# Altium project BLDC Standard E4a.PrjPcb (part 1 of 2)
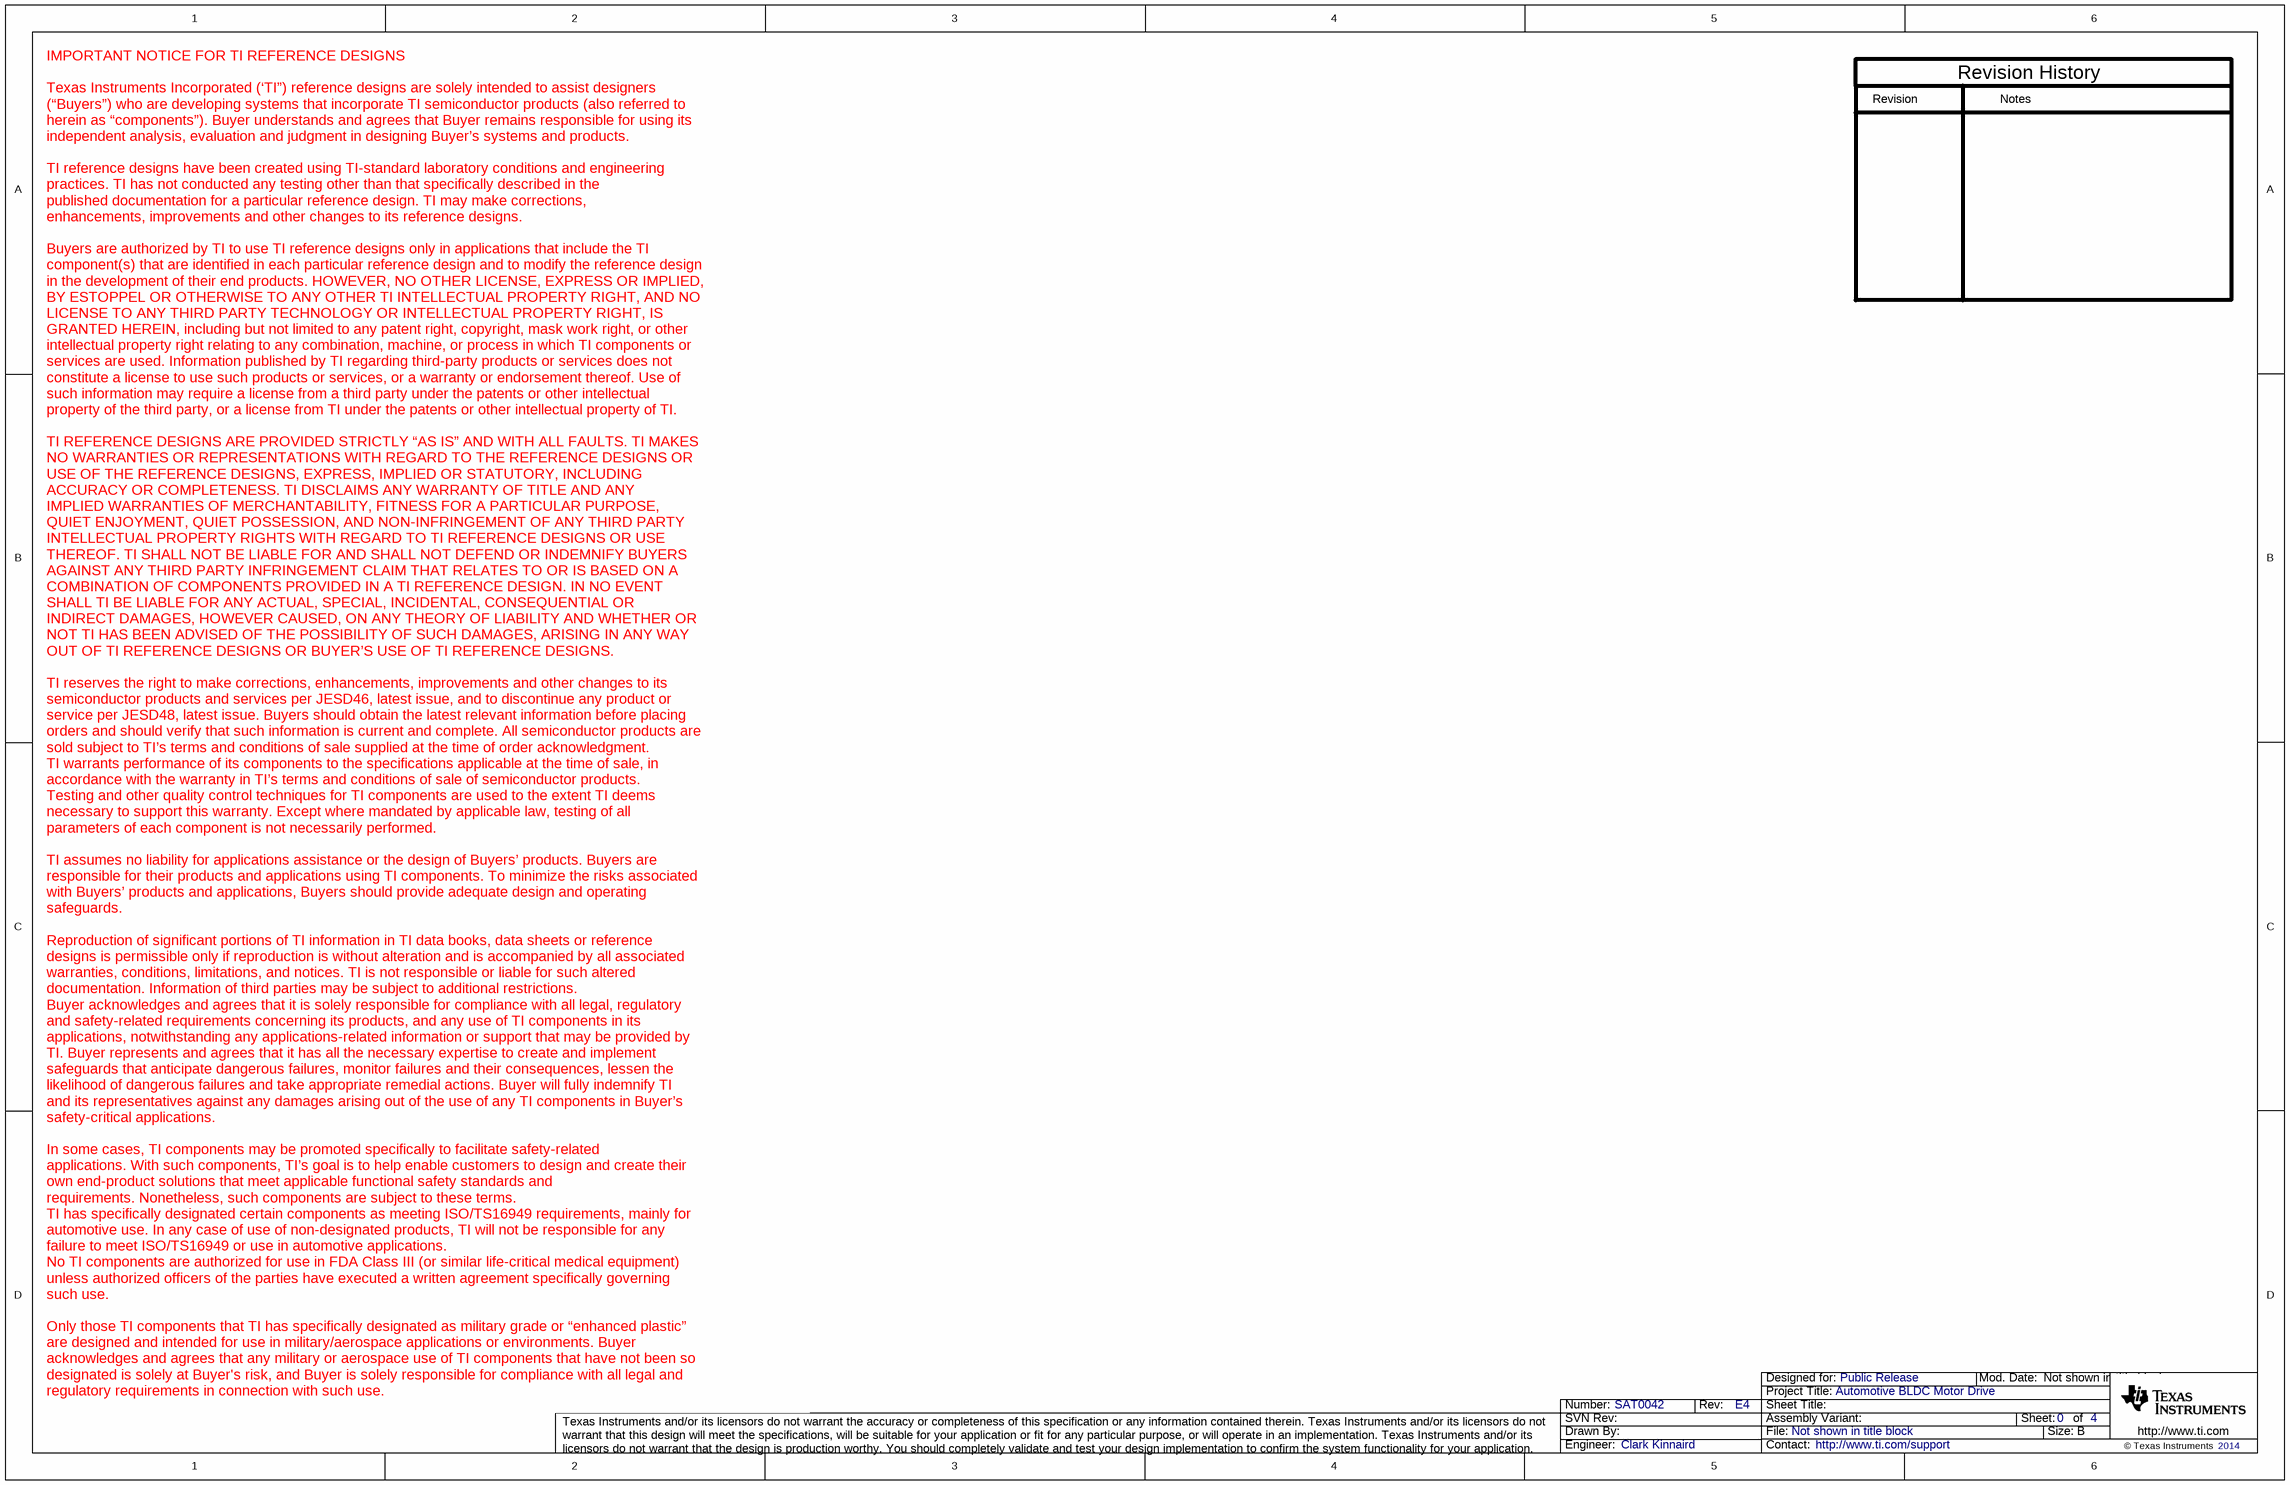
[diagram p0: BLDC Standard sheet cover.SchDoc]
CopyrightYear: 2014; PCB_Layout: Krypton Solutions LLC; PCB_Rev: E4; PRJ_Customer: Public Release; PRJ_Engineer: Clark Kinnaird; PRJ_Number: SAT0042; PRJ_Title: Automotive BLDC Motor Drive; SCH_Rev: E4; TechSupport: http://www.ti.com/support
6 sheets, 212 parts. Net scope: global (net labels, ports and power ports of the same name join across sheets).
Board file: BLDC Standard.PcbDoc
Sheets:
  BLDC Standard sheet cover.SchDoc
  Hardware_ANSI-B.SchDoc
  BLDC Standard sheet 1.SchDoc
  BLDC Standard sheet 2.SchDoc
  BLDC Standard sheet 3.SchDoc
  BLDC Standard sheet 4.SchDoc

## Sheet BLDC Standard sheet cover.SchDoc
size 431 x 279 mm; Date: Not shown in title block; ApprovedBy: Not shown in title block; CheckedBy: Not shown in title block; Author: Not shown in title block; CompanyName: Not shown in title block; Engineer: Not shown in title block; Organization: Not shown in title block; Address1: Not shown in title block; Address2: Not shown in title block; Address3: Not shown in title block; Address4: Not shown in title block; DocumentNumber: 1; Revision: Use project parameter SCH_Rev; SheetNumber: 0; SheetTotal: 4; PageSetup: Record=PageOptions|CenterHorizontal=True|CenterVertical=True|PrintScale=0.64|XCorrection=1.00|YCorrection=1.00|PrintKind=0|BorderSize=5000000|LeftOffset=0|BottomOffset=0|Orientation=2|PaperLength=1000|PaperWidth=1000|Scale=100|PaperSource=15|PrintQuality=600|MediaType=1|DitherType=10|PaperKind=11x17|PrintScaleMode=1

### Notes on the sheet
- Revision
- Notes
- Revision History
- IMPORTANT NOTICE FOR TI REFERENCE DESIGNS
  Texas Instruments Incorporated (‘TI”) reference designs are solely intended to assist designers
  (“Buyers”) who are developing systems that incorporate TI semiconductor products (also referred to
  herein as “components”). Buyer understands and agrees that Buyer remains responsible for using its
  independent analysis, evaluation and judgment in designing Buyer’s systems and products.
  TI reference designs have been created using TI-standard laboratory conditions and engineering
  practices. TI has not conducted any testing other than that specifically described in the
  published documentation for a particular reference design. TI may make corrections,
  enhancements, improvements and other changes to its reference designs.
  Buyers are authorized by TI to use TI reference designs only in applications that include the TI
  component(s) that are identified in each particular reference design and to modify the reference design
  in the development of their end products. HOWEVER, NO OTHER LICENSE, EXPRESS OR IMPLIED,
  BY ESTOPPEL OR OTHERWISE TO ANY OTHER TI INTELLECTUAL PROPERTY RIGHT, AND NO
  LICENSE TO ANY THIRD PARTY TECHNOLOGY OR INTELLECTUAL PROPERTY RIGHT, IS
  GRANTED HEREIN, including but not limited to any patent right, copyright, mask work right, or other
  intellectual property right relating to any combination, machine, or process in which TI components or
  services are used. Information published by TI regarding third-party products or services does not
  constitute a license to use such products or services, or a warranty or endorsement thereof. Use of
  such information may require a license from a third party under the patents or other intellectual
  property of the third party, or a license from TI under the patents or other intellectual property of TI.
  TI REFERENCE DESIGNS ARE PROVIDED STRICTLY “AS IS” AND WITH ALL FAULTS. TI MAKES
  NO WARRANTIES OR REPRESENTATIONS WITH REGARD TO THE REFERENCE DESIGNS OR
  USE OF THE REFERENCE DESIGNS, EXPRESS, IMPLIED OR STATUTORY, INCLUDING
  ACCURACY OR COMPLETENESS. TI DISCLAIMS ANY WARRANTY OF TITLE AND ANY
  IMPLIED WARRANTIES OF MERCHANTABILITY, FITNESS FOR A PARTICULAR PURPOSE,
  QUIET ENJOYMENT, QUIET POSSESSION, AND NON-INFRINGEMENT OF ANY THIRD PARTY
  INTELLECTUAL PROPERTY RIGHTS WITH REGARD TO TI REFERENCE DESIGNS OR USE
  THEREOF. TI SHALL NOT BE LIABLE FOR AND SHALL NOT DEFEND OR INDEMNIFY BUYERS
  AGAINST ANY THIRD PARTY INFRINGEMENT CLAIM THAT RELATES TO OR IS BASED ON A
  COMBINATION OF COMPONENTS PROVIDED IN A TI REFERENCE DESIGN. IN NO EVENT
  SHALL TI BE LIABLE FOR ANY ACTUAL, SPECIAL, INCIDENTAL, CONSEQUENTIAL OR
  INDIRECT DAMAGES, HOWEVER CAUSED, ON ANY THEORY OF LIABILITY AND WHETHER OR
  NOT TI HAS BEEN ADVISED OF THE POSSIBILITY OF SUCH DAMAGES, ARISING IN ANY WAY
  OUT OF TI REFERENCE DESIGNS OR BUYER’S USE OF TI REFERENCE DESIGNS.
  TI reserves the right to make corrections, enhancements, improvements and other changes to its
  semiconductor products and services per JESD46, latest issue, and to discontinue any product or
  service per JESD48, latest issue. Buyers should obtain the latest relevant information before placing
  orders and should verify that such information is current and complete. All semiconductor products are
  sold subject to TI’s terms and conditions of sale supplied at the time of order acknowledgment.
  TI warrants performance of its components to the specifications applicable at the time of sale, in
  accordance with the warranty in TI’s terms and conditions of sale of semiconductor products.
  Testing and other quality control techniques for TI components are used to the extent TI deems
  necessary to support this warranty. Except where mandated by applicable law, testing of all
  parameters of each component is not necessarily performed.
  TI assumes no liability for applications assistance or the design of Buyers’ products. Buyers are
  responsible for their products and applications using TI components. To minimize the risks associated
  with Buyers’ products and applications, Buyers should provide adequate design and operating
  safeguards.
  Reproduction of significant portions of TI information in TI data books, data sheets or reference
  designs is permissible only if reproduction is without alteration and is accompanied by all associated
  warranties, conditions, limitations, and notices. TI is not responsible or liable for such altered
  documentation. Information of third parties may be subject to additional restrictions.
  Buyer acknowledges and agrees that it is solely responsible for compliance with all legal, regulatory
  and safety-related requirements concerning its products, and any use of TI components in its
  applications, notwithstanding any applications-related information or support that may be provided by
  TI. Buyer represents and agrees that it has all the necessary expertise to create and implement
  safeguards that anticipate dangerous failures, monitor failures and their consequences, lessen the
  likelihood of dangerous failures and take appropriate remedial actions. Buyer will fully indemnify TI
  and its representatives against any damages arising out of the use of any TI components in Buyer’s
  safety-critical applications.
  In some cases, TI components may be promoted specifically to facilitate safety-related
  applications. With such components, TI’s goal is to help enable customers to design and create their
  own end-product solutions that meet applicable functional safety standards and
  requirements. Nonetheless, such components are subject to these terms.
  TI has specifically designated certain components as meeting ISO/TS16949 requirements, mainly for
  automotive use. In any case of use of non-designated products, TI will not be responsible for any
  failure to meet ISO/TS16949 or use in automotive applications.
  No TI components are authorized for use in FDA Class III (or similar life-critical medical equipment)
  unless authorized officers of the parties have executed a written agreement specifically governing
  such use.
  Only those TI components that TI has specifically designated as military grade or “enhanced plastic”
  are designed and intended for use in military/aerospace applications or environments. Buyer
  acknowledges and agrees that any military or aerospace use of TI components that have not been so
  designated is solely at Buyer's risk, and Buyer is solely responsible for compliance with all legal and
  regulatory requirements in connection with such use.

## Sheet Hardware_ANSI-B.SchDoc: Hardware
size 431 x 279 mm; Date: Not shown in title block; ApprovedBy: Not shown in title block; CheckedBy: Not shown in title block; Author: Not shown in title block; CompanyName: Not shown in title block; Engineer: Not shown in title block; Organization: Not shown in title block; Address1: Not shown in title block; Address2: Not shown in title block; Address3: Not shown in title block; Address4: Not shown in title block; DocumentNumber: 1; Revision: Use project parameter SCH_Rev; SheetNumber: 4; SheetTotal: 4; PageSetup: Record=PageOptions|CenterHorizontal=True|CenterVertical=True|PrintScale=1.00|XCorrection=1.00|YCorrection=1.00|PrintKind=0|BorderSize=5000000|LeftOffset=0|BottomOffset=0|Orientation=2|PaperLength=1000|PaperWidth=1000|Scale=100|PaperSource=15|PrintQuality=600|MediaType=1|DitherType=10|PaperKind=Letter|PrintScaleMode=1
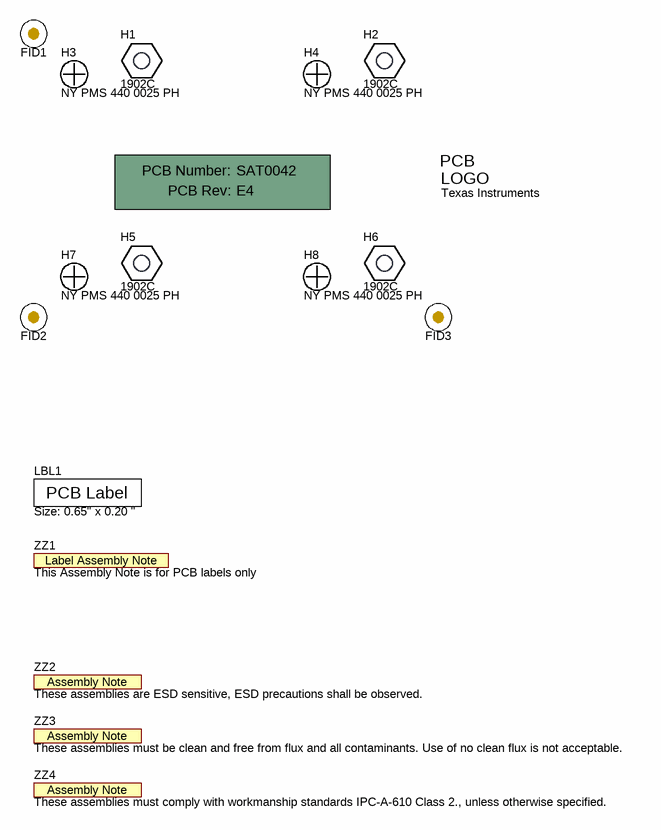
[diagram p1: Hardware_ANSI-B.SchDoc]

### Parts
!PCB1  Printed Circuit Board  (value not drawn)  (mechanical)
FID1  Fiducial  [Fiducial10-20]  (value not drawn)
FID2  Fiducial  [Fiducial10-20]  (value not drawn)
FID3  Fiducial  [Fiducial10-20]  (value not drawn)
H1  1902C  [Keystone_1902C]
H2  1902C  [Keystone_1902C]
H3  NY PMS 440 0025 PH  [NY PMS 440 0025 PH]
H4  NY PMS 440 0025 PH  [NY PMS 440 0025 PH]
H5  1902C  [Keystone_1902C]
H6  1902C  [Keystone_1902C]
H7  NY PMS 440 0025 PH  [NY PMS 440 0025 PH]
H8  NY PMS 440 0025 PH  [NY PMS 440 0025 PH]
LBL1  Size: 0.65" x 0.20 "  [Label_650x200]
Logo1  Texas Instruments  [TI_Stacked_SolderMask_Small]  (no BOM)
ZZ1  This Assembly Note is for PCB labels only  [AssemblyNoteLabel]  (no BOM)
ZZ2  These assemblies are ESD sensitive, ESD precautions shall be observed.  [AssemblyNote]  (no BOM)
ZZ3  These assemblies must be clean and free from flux and all contaminants. Use of no clean flux is not acceptable.  [AssemblyNote]  (no BOM)
ZZ4  These assemblies must comply with workmanship standards IPC-A-610 Class 2., unless otherwise specified.  [AssemblyNote]  (no BOM)

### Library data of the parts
!PCB1 = PCB: Manufacturer: Any; PartNumber: SAT0042; SymbolCreator: a0412235
FID1-FID3 = Fiducial: Fiducial mark.  There is nothing to buy or mount.; SymbolCreator: codlsc
H1 H2 H5 H6 = 1902C: Standoff, Hex, 0.5"L #4-40 Nylon; Manufacturer: Keystone; CompType: Hardware
H3 H4 H7 H8 = NY PMS 440 0025 PH: Machine Screw, Round, #4-40 x 1/4, Nylon, Philips panhead; Manufacturer: B&F Fastener Supply; CompType: Hardware; SymbolCreator: codlsc; U/M: EA
LBL1 = THT-14-423-10: Thermal Transfer Printable Labels, 0.650" W x 0.200" H - 10,000 per roll; Manufacturer: Brady; SymbolCreator: a0412235; CompType: Label
Logo1 = TI_Logo: Texas Instrument Corporate Signature; SymbolCreator: codlsc
ZZ1 = AssemblyNoteLabel: SymbolCreator: a0412235
ZZ2-ZZ4 = AssemblyNote: SymbolCreator: codlsc

## Sheet BLDC Standard sheet 1.SchDoc
size 431 x 279 mm; Date: Not shown in title block; ApprovedBy: Not shown in title block; CheckedBy: Not shown in title block; Author: Not shown in title block; CompanyName: Not shown in title block; Engineer: Not shown in title block; Organization: Not shown in title block; Address1: Not shown in title block; Address2: Not shown in title block; Address3: Not shown in title block; Address4: Not shown in title block; DocumentNumber: 1; Revision: Use project parameter SCH_Rev; SheetNumber: 1; SheetTotal: 4; PageSetup: Record=PageOptions|CenterHorizontal=True|CenterVertical=True|PrintScale=0.96|XCorrection=1.00|YCorrection=1.00|PrintKind=0|BorderSize=5000000|LeftOffset=0|BottomOffset=0|Orientation=2|PaperLength=1000|PaperWidth=1000|Scale=100|PaperSource=15|PrintQuality=600|MediaType=1|DitherType=10|PaperKind=11x17|PrintScaleMode=1
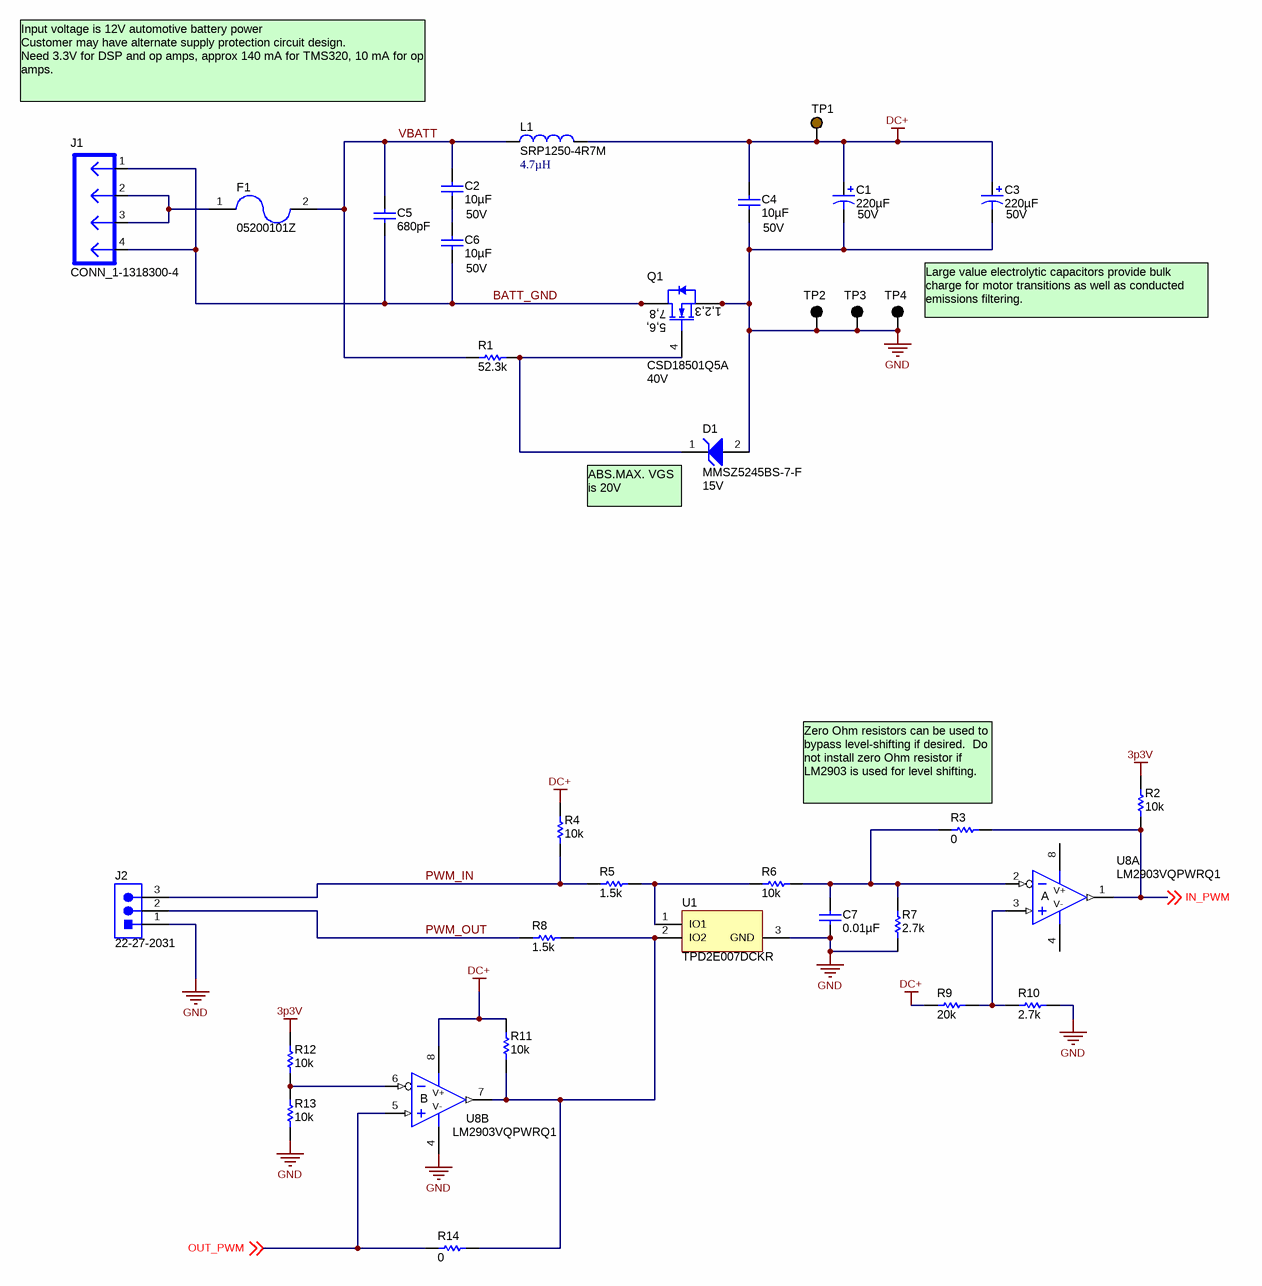
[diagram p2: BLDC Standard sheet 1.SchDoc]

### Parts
C1  ValueDisplayed: 220µF  Value2: 50V  [CAPSMT_62_KE0]  (hidden comment: EMVH500ARA221MKE0S)
C2  ValueDisplayed: 10µF  Value2: 50V  [1210]  (hidden comment: GRM32ER71H106KA12L)
C3  ValueDisplayed: 220µF  Value2: 50V  [CAPSMT_62_KE0]  (hidden comment: EMVH500ARA221MKE0S)
C4  ValueDisplayed: 10µF  Value2: 50V  [1210]  (hidden comment: GRM32ER71H106KA12L)
C5  ValueDisplayed: 680pF  [0805_HV]  (hidden comment: 08055A681JAT2A)
C6  ValueDisplayed: 10µF  Value2: 50V  [1210]  (hidden comment: GRM32ER71H106KA12L)
C7  ValueDisplayed: 0.01µF  [0603]  (hidden comment: 06031C103JAT2A)
D1  MMSZ5245BS-7-F  value 15V  [sod-323]
F1  05200101Z  [05200101Z]
J1  CONN_1-1318300-4  [CONN_1-1318300-4]
J2  22-27-2031  [MOLEX_22-27-2031]
L1  SRP1250-4R7M  Inductance: 4.7µH  [SRP1250-4R7MTR]
Q1  CSD18501Q5A  value 40V  [TRANS_NexFET_Q5A]
R1  value 52.3k  [0603]  (hidden comment: CRCW060352K3FKEA)
R2  value 10k  [0603]  (hidden comment: CRCW060310K0JNEA)
R3  value 0  [0603]  (hidden comment: ERJ-3GEY0R00V)
R4  value 10k  [0603]  (hidden comment: CRCW060310K0JNEA)
R5  value 1.5k  [0603]  (hidden comment: CRCW06031K50JNEA)
R6  value 10k  [0402]  (hidden comment: CRCW040210K0JNED)
R7  value 2.7k  [0603]  (hidden comment: CRCW06032K70JNEA)
R8  value 1.5k  [0603]  (hidden comment: CRCW06031K50JNEA)
R9  value 20k  [0603]  (hidden comment: CRCW060320K0JNEA)
R10  value 2.7k  [0603]  (hidden comment: CRCW06032K70JNEA)
R11  value 10k  [0603]  (hidden comment: CRCW060310K0JNEA)
R12  value 10k  [0603]  (hidden comment: CRCW060310K0JNEA)
R13  value 10k  [0603]  (hidden comment: CRCW060310K0JNEA)
R14  value 0  [0603]  (hidden comment: ERJ-3GEY0R00V)
TP1  5125  [Keystone5125]  (value not drawn)
TP2  5011  [Keystone5011]  (value not drawn)
TP3  5011  [Keystone5011]  (value not drawn)
TP4  5011  [Keystone5011]  (value not drawn)
U1  TPD2E007DCKR  [DCK0003A_N]
U8  LM2903VQPWRQ1  [PW0008A_N]  (parts A,B of 2)

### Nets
3p3V: R2.2 R12.2
DC+: C1.1(+) C3.1(+) C4.1 L1.2 R4.2 R9.2 R11.2 TP1.1 U8.8(V+)
GND: C1.2(-) C3.2(-) C4.2 C7.2 D1.2(A) J2.1 Q1.1(S) Q1.2(S) Q1.3(S) R7.1 R10.2 R13.1 TP2.1 TP3.1 TP4.1 U1.3(GND) U8.4(V-)
BATT_GND: C5.2 C6.2 J1.1 J1.4 Q1.5(D) Q1.6(D) Q1.7(D) Q1.8(D) Q1.9(D)
IN_PWM: R2.1 R3.2 U8.1(OUT) ; off-sheet IN_PWM
OUT_PWM: R14.1 U8.5(IN+) ; off-sheet OUT_PWM
PWM_IN: J2.3 R4.1 R5.1
PWM_OUT: J2.2 R8.1
VBATT: C2.1 C5.1 F1.2 L1.1 R1.2
NetC2_2: C2.2 C6.1
NetC7_1: C7.1 R3.1 R6.1 R7.2 U8.2(IN-)
NetD1_1: D1.1(K) Q1.4(G) R1.1
NetF1_1: F1.1 J1.2 J1.3
NetR5_2: R5.2 R6.2 U1.1(IO1)
NetR8_2: R8.2 R11.1 R14.2 U1.2(IO2) U8.7(OUT)
NetR9_1: R9.1 R10.1 U8.3(IN+)
NetR12_1: R12.1 R13.2 U8.6(IN-)

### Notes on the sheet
- Input voltage is 12V automotive battery power
  Customer may have alternate supply protection circuit design.
  Need 3.3V for DSP and op amps, approx 140 mA for TMS320, 10 mA for op amps.
- (near TP4) Large value electrolytic capacitors provide bulk charge for motor transitions as well as conducted emissions filtering.
- (near D1) ABS.MAX. VGS is 20V
- (near R3) Zero Ohm resistors can be used to bypass level-shifting if desired.  Do not install zero Ohm resistor if LM2903 is used for level shifting.

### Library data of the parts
C1 C3 = EMVH500ARA221MKE0S: CAP, AL, 220uF, 50V, +/-20%, 0.23 ohm, SMD; Manufacturer: Nippon Chemi-Con; Polarized: Y; CompType: Capacitor; U/M: EA; Cap_F: 0.00022; Tolerance_%: 20; VDC_V: 50; ESR_Ohm: 0.23; IRMS_A: 0.55; TaMin_C: -40; TaMax_C: 125; Cap_Case: KE0
C2 C4 C6 = GRM32ER71H106KA12L: CAP, CERM, 10uF, 50V, +/-10%, X7R, 1210; Manufacturer: MuRata; Polarized: N; CompType: Capacitor; U/M: EA; Cap_F: 0.00001; Tolerance_%: 10; Value1: Unknown; VDC_V: 50; TaMin_C: -55; TaMax_C: 125
C5 = 08055A681JAT2A: CAP, CERM, 680pF, 50V, +/-5%, C0G/NP0, 0805; Manufacturer: AVX; Polarized: N; CompType: Capacitor; U/M: EA; Cap_F: 0.00000000068; Tolerance_%: 5; ESR_Ohm: 0.134; Value1: 0.134 ohm; VDC_V: 50; TaMin_C: -55; TaMax_C: 125; Cap_Case: 0805
C7 = 06031C103JAT2A: CAP, CERM, 0.01uF, 100V, +/-5%, X7R, 0603; Manufacturer: AVX; Polarized: N; CompType: Capacitor; U/M: EA; Cap_F: 0.00000001; Tolerance_%: 5; ESR_Ohm: 0.098; Value1: 0.098 ohm; VDC_V: 100; TaMin_C: -55; TaMax_C: 125
D1 = MMSZ5245BS-7-F: Diode, Zener, 15V, 200mW, SOD-323; Manufacturer: Diodes Inc.; U/M: EA; Power_W: 0.2; Vz_V: 15; Value1: 0.2W; RJA_CperW: 350
F1 = 05200101Z: FUSE BLOK CARTRIDGE 300V 10A PCB; Manufacturer: Littelfuse Inc; Fuseholder Type: Block; For Use With/Related Products: 5mm x 20mm; Number of Circuits: 1
J1 = CONN_1-1318300-4: Connector, Vertical, 0.156 mil; Manufacturer: Tyco; Area: 185000
J2 = 22-27-2031: CONN HEADER 3POS .100 VERT TIN; Manufacturer: Molex; SymbolCreator: a0799628; U/M: EA
L1 = SRP1250-4R7MTR: INDUCTOR POWER 4.7UH 12A SMD; Manufacturer: Bourns Inc.; Type: Iron Core; Current - Saturation: 27A; Tolerance: ±20%; Material - Core: Iron; Shielding: Shielded; DC Resistance (DCR): 15 mOhm Max; Frequency - Test: 100kHz
Q1 = CSD18501Q5A: MOSFET, N-CH, 40V, 22A, SON 5x6mm; Manufacturer: Texas Instruments; Alternate Manufacturer: None; U/M: EA; ChType: N; VdsMax_V: 40; Value1: 0.0043 ohm; Rdson45_Ohm: 0.0043; Value2: 20 nC; QgTyp_nC: 20; IdsMax_A: 22
R1 = CRCW060352K3FKEA: RES, 52.3k ohm, 1%, 0.1W, 0603; Manufacturer: Vishay-Dale; CompType: Resistor; Res_ohm: 52300; Value_Code: 52k3; Tolerance_%: 1; Power_W: 0.1; VDC_V: 75; TempCo: 100 ppm/C; EIA_Code: E96; U/M: EA
R2 R4 R11-R13 = CRCW060310K0JNEA: RES, 10k ohm, 5%, 0.1W, 0603; Manufacturer: Vishay-Dale; CompType: Resistor; Res_ohm: 10000; Value_Code: 10k0; Tolerance_%: 5; Power_W: 0.1; VDC_V: 75; TempCo: 200 ppm/C; EIA_Code: E24; U/M: EA
R3 R14 = ERJ-3GEY0R00V: RES, 0 ohm, 5%, 0.1W, 0603; Manufacturer: Panasonic; CompType: Resistor; Value_Code: 0000; Tolerance_%: 5; Power_W: 0.1; VDC_V: 50; TempCo: 600 ppm/C; EIA_Code: E24; U/M: EA
R5 R8 = CRCW06031K50JNEA: RES, 1.5k ohm, 5%, 0.1W, 0603; Manufacturer: Vishay-Dale; CompType: Resistor; Res_ohm: 1500; Value_Code: 1k50; Tolerance_%: 5; Power_W: 0.1; VDC_V: 75; TempCo: 200 ppm/C; EIA_Code: E24; U/M: EA
R6 = CRCW040210K0JNED: RES, 10k ohm, 5%, 0.063W, 0402; Manufacturer: Vishay-Dale; CompType: Resistor; Res_ohm: 10000; Value_Code: 10k0; Tolerance_%: 5; Power_W: 0.063; VDC_V: 50; TempCo: 200 ppm/C; EIA_Code: E24; U/M: EA
R7 R10 = CRCW06032K70JNEA: RES, 2.7k ohm, 5%, 0.1W, 0603; Manufacturer: Vishay-Dale; CompType: Resistor; Res_ohm: 2700; Value_Code: 2k70; Tolerance_%: 5; Power_W: 0.1; VDC_V: 75; TempCo: 200 ppm/C; EIA_Code: E24; U/M: EA
R9 = CRCW060320K0JNEA: RES, 20k ohm, 5%, 0.1W, 0603; Manufacturer: Vishay-Dale; CompType: Resistor; Res_ohm: 20000; Value_Code: 20k0; Tolerance_%: 5; Power_W: 0.1; VDC_V: 75; TempCo: 200 ppm/C; EIA_Code: E24; U/M: EA
TP1 = 5125: Test Point, Multipurpose, Brown, TH; Manufacturer: Keystone; SymbolCreator: a0412235; CompType: Test Point Loop; U/M: EA
TP2-TP4 = 5011: Test Point, Multipurpose, Black, TH; Manufacturer: Keystone; CompType: Test Point Loop; U/M: EA
U1 = TPD2E007DCKR: ESD Protection Array for AC Signal Data Interface, 2 Channels, -40 to +85 degC, 3-pin SC70 (DCK), Green (RoHS & no Sb/Br); Manufacturer: Texas Instruments; Alternate Manufacturer: None; Alternate PartNumber: Equivalent; Breakdown Voltage(Min)(V): +/-14; IEC 61000-4-2 Air-Gap(+/- kV): 15; IEC 61000-4-2 Contact(+/- kV): 8; IO Leakage Current(nA): 50; SubFamily: ESD Solution
U8 = LM2903VQPWRQ1: DUAL DIFFERENTIAL COMPARATORS, PW0008A; Alternate Manufacturer: None; Manufacturer: Texas Instruments; SymbolCreator: a0799628; CompType: IC; U/M: EA

## Sheet BLDC Standard sheet 2.SchDoc
size 431 x 279 mm; Date: Not shown in title block; ApprovedBy: Not shown in title block; CheckedBy: Not shown in title block; Author: Not shown in title block; CompanyName: Not shown in title block; Engineer: Not shown in title block; Organization: Not shown in title block; Address1: Not shown in title block; Address2: Not shown in title block; Address3: Not shown in title block; Address4: Not shown in title block; DocumentNumber: 1; Revision: Use project parameter SCH_Rev; SheetNumber: 2; SheetTotal: 4; PageSetup: Record=PageOptions|CenterHorizontal=True|CenterVertical=True|PrintScale=0.96|XCorrection=1.00|YCorrection=1.00|PrintKind=0|BorderSize=5000000|LeftOffset=0|BottomOffset=0|Orientation=2|PaperLength=1000|PaperWidth=1000|Scale=100|PaperSource=15|PrintQuality=600|MediaType=1|DitherType=10|PaperKind=11x17|PrintScaleMode=1
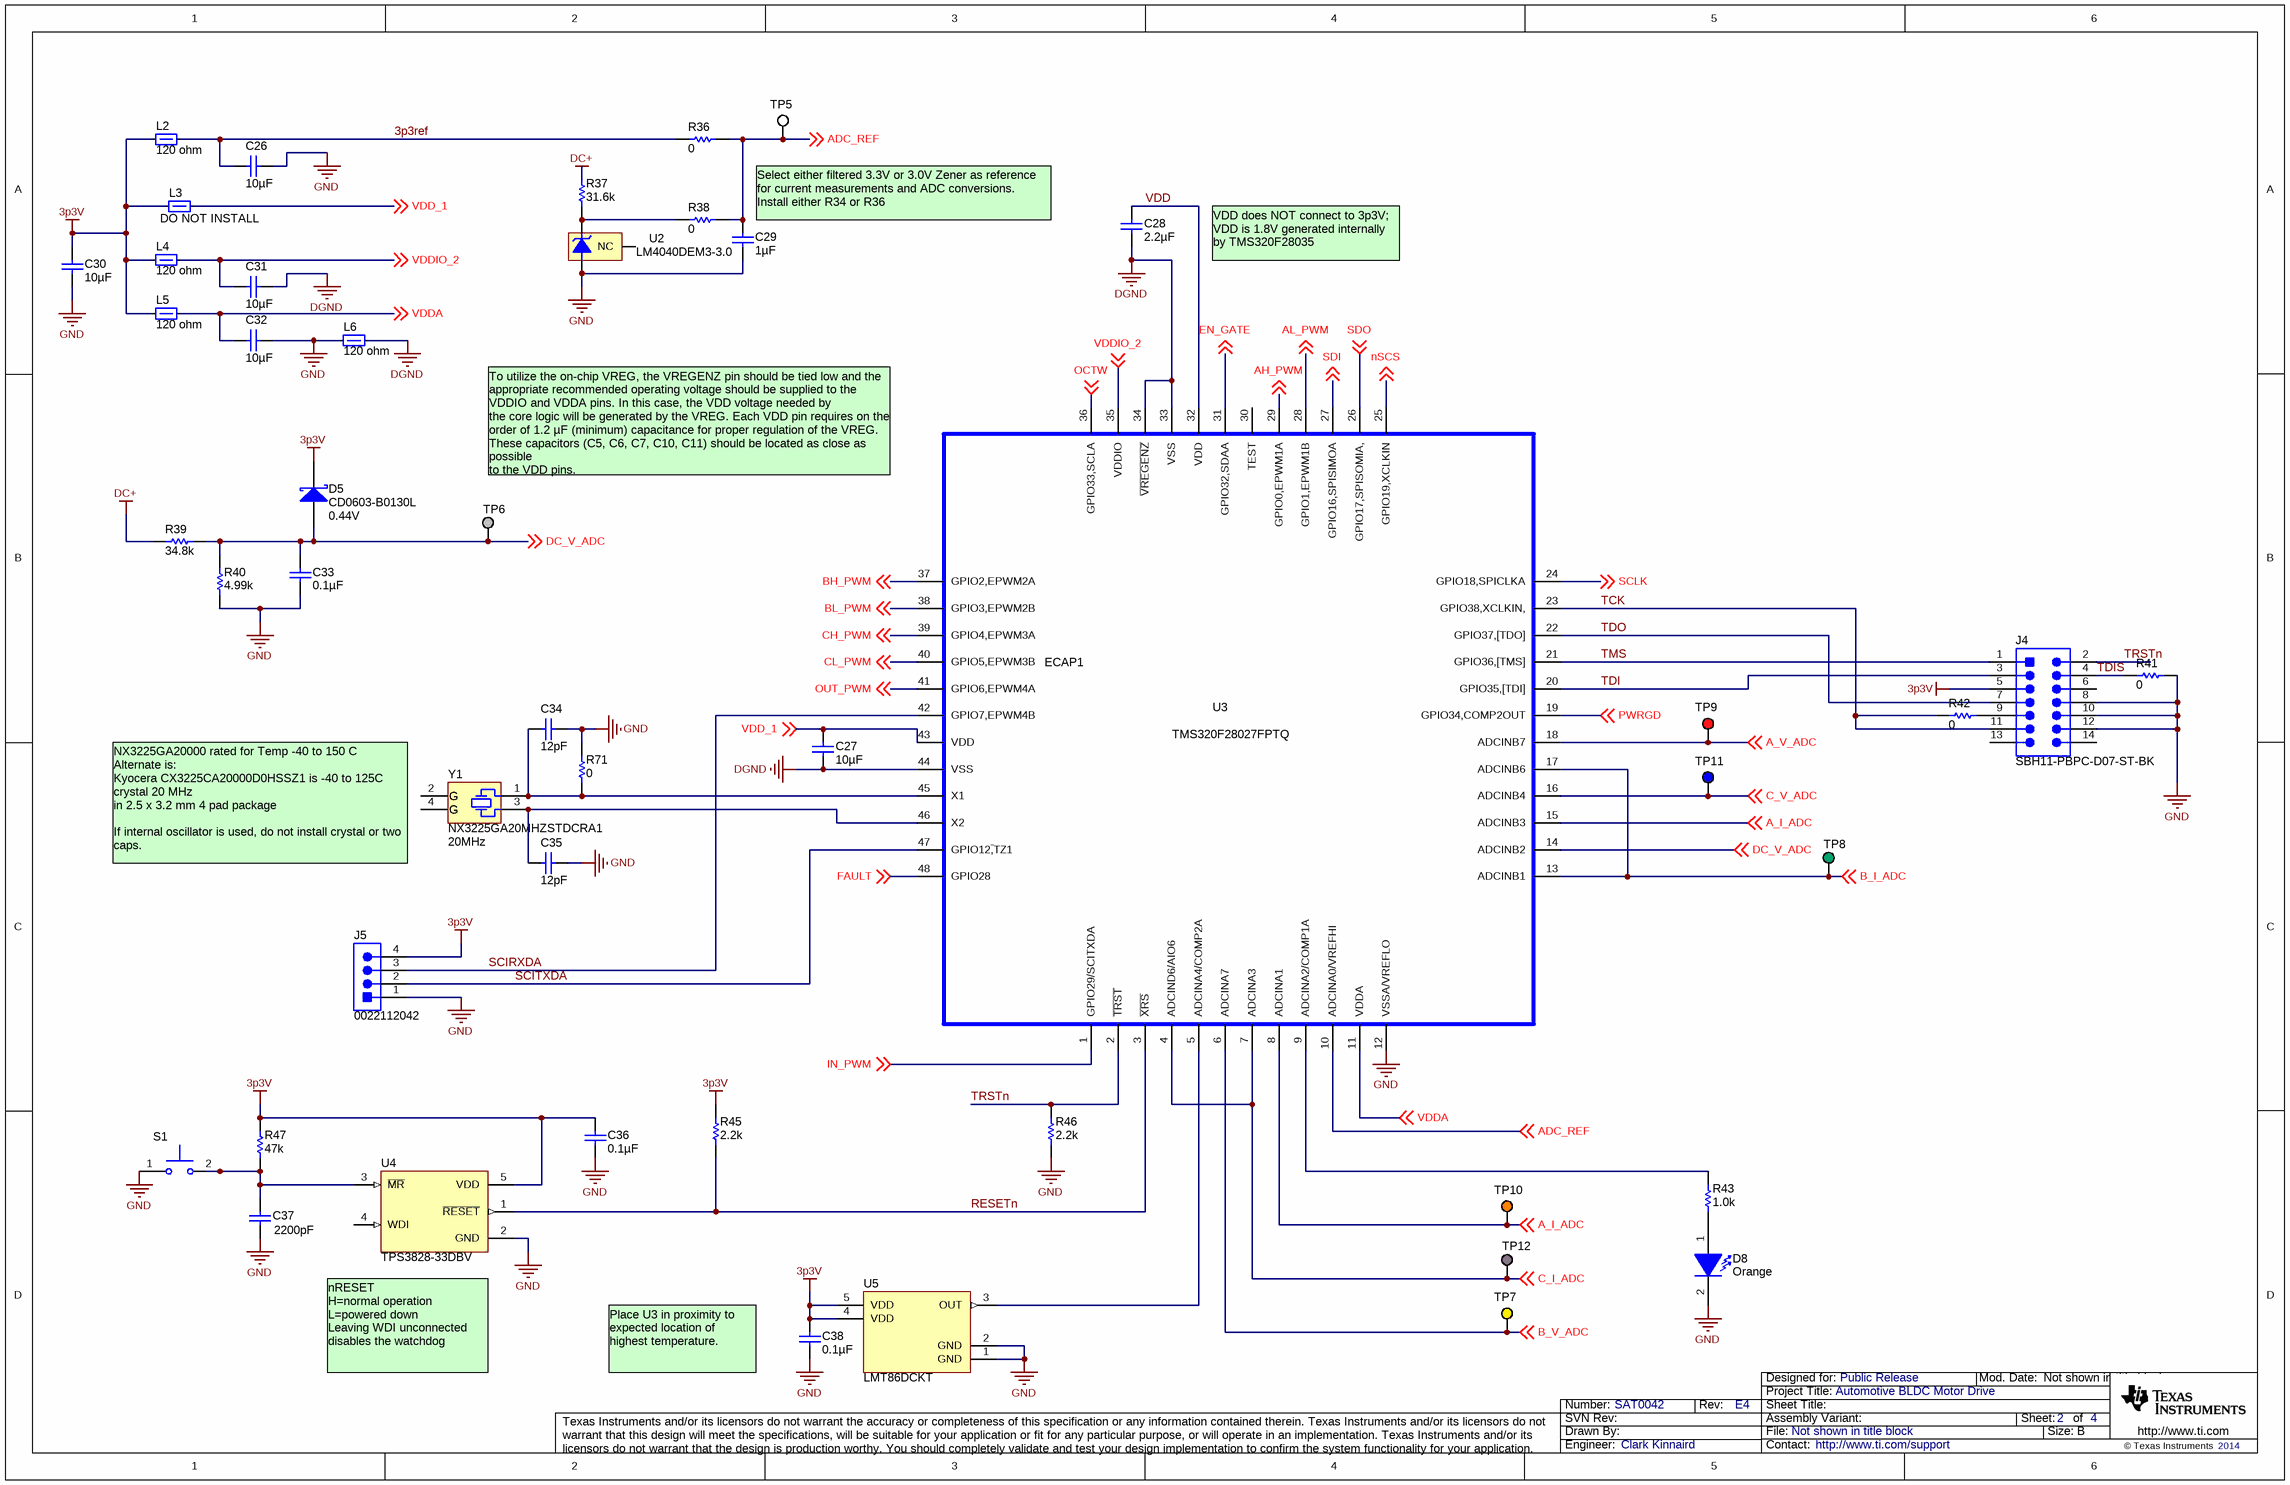
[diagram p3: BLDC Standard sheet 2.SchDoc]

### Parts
C26  ValueDisplayed: 10µF  [0603]  (hidden comment: GRM188R60J106ME47D)
C27  ValueDisplayed: 10µF  [0603]  (hidden comment: GRM188R60J106ME47D)
C28  ValueDisplayed: 2.2µF  [0603]  (hidden comment: GRM188R71A225KE15D)
C29  ValueDisplayed: 1µF  [0603]  (hidden comment: C1608X7R1C105K)
C30  ValueDisplayed: 10µF  [0603]  (hidden comment: GRM188R60J106ME47D)
C31  ValueDisplayed: 10µF  [0603]  (hidden comment: GRM188R60J106ME47D)
C32  ValueDisplayed: 10µF  [0603]  (hidden comment: GRM188R60J106ME47D)
C33  ValueDisplayed: 0.1µF  [0805_HV]  (hidden comment: C0805C104K4RACTU)
C34  ValueDisplayed: 12pF  [0603]  (hidden comment: 06035A120JAT2A)
C35  ValueDisplayed: 12pF  [0603]  (hidden comment: 06035A120JAT2A)
C36  ValueDisplayed: 0.1µF  [0603]  (hidden comment: GCM188R71H104KA57B)
C37  value 2200pF  [0402]  (hidden comment: UMK105B7222KV-F)
C38  ValueDisplayed: 0.1µF  [0805_HV]  (hidden comment: C0805C104K4RACTU)
D5  CD0603-B0130L  value 0.44V  [Diode_0603]
D8  value Orange  [LED_LTST-C190]  (hidden comment: LTST-C190KFKT)
J4  SBH11-PBPC-D07-ST-BK  [CONN_SBH11-PBPC-D07-ST-BK]
J5  0022112042  [CONN_22112042]
L2  value 120 ohm  [0603]  (hidden comment: BLM18SG121TN1D)
L3  DO NOT INSTALL  [0603]
L4  value 120 ohm  [0603]  (hidden comment: BLM18SG121TN1D)
L5  value 120 ohm  [0603]  (hidden comment: BLM18SG121TN1D)
L6  value 120 ohm  [0603]  (hidden comment: BLM18SG121TN1D)
R36  value 0  [0603]  (hidden comment: ERJ-3GEY0R00V)
R37  value 31.6k  [0603]  (hidden comment: CRCW060331K6FKEA)
R38  value 0  [0603]  (hidden comment: ERJ-3GEY0R00V)
R39  value 34.8k  [0603]  (hidden comment: CRCW060334K8FKEA)
R40  value 4.99k  [0603]  (hidden comment: CRCW06034K99FKEA)
R41  value 0  [0603]  (hidden comment: ERJ-3GEY0R00V)
R42  value 0  [0603]  (hidden comment: ERJ-3GEY0R00V)
R43  value 1.0k  [0603]  (hidden comment: CRCW06031K00JNEA)
R45  value 2.2k  [0603]  (hidden comment: CRCW06032K20JNEA)
R46  value 2.2k  [0603]  (hidden comment: CRCW06032K20JNEA)
R47  value 47k  [0402]  (hidden comment: CRCW040247K0JNED)
R71  value 0  [0603]  (hidden comment: ERJ-3GEY0R00V)
S1  SKRKAEE010  [SW_SKRKAEE010]  (value not drawn)
TP5  5012  [Keystone5012]  (value not drawn)
TP6  5128  [Keystone5128]  (value not drawn)
TP7  5014  [Keystone5014]  (value not drawn)
TP8  5126  [Keystone5126]  (value not drawn)
TP9  5010  [Keystone5010]  (value not drawn)
TP10  5013  [Keystone5013]  (value not drawn)
TP11  5127  [Keystone5127]  (value not drawn)
TP12  5129  [Keystone5129]  (value not drawn)
U2  LM4040DEM3-3.0  [MF03A_N]
U3  TMS320F28027FPTQ  [PT-48]
U4  TPS3828-33DBV  [DBV0005A_N]
U5  LMT86DCKT  [DCK0005A_N]
Y1  NX3225GA20MHZSTDCRA1  Frequency: 20MHz  [XTAL_NX3225SA]

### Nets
3p3V: C30.2 C36.1 C38.1 D5.1(K) J4.5 J5.4 L2.1 L3.1 L4.1 L5.1 R45.2 R47.2 U4.5(VDD) U5.4(VDD) U5.5(VDD)
DC+: R37.2 R39.1
DGND: C27.2 C28.2 C31.2 L6.2 U3.33(VSS) U3.34(~{VREGENZ}) U3.44(VSS)
GND: C26.2 C29.2 C30.1 C32.2 C33.2 C34.2 C35.2 C36.2 C37.2 C38.2 D8.2(K) J4.8 J4.10 J4.12 J5.1 L6.1 R40.1 R41.1 R46.1 R71.2 S1.1 U2.2(-V) U3.12(VSSA/VREFLO) U4.2(GND) U5.1(GND) U5.2(GND)
3p3ref: C26.1 L2.2 R36.1
A_I_ADC: TP10.1 U3.8(ADCINA1) U3.15(ADCINB3) ; off-sheet A_I_ADC
A_V_ADC: TP9.1 U3.18(ADCINB7) ; off-sheet A_V_ADC
ADC_REF: C29.1 R36.2 R38.2 TP5.1 U3.10(ADCINA0/VREFHI) ; off-sheet ADC_REF
AH_PWM: U3.29(GPIO0,EPWM1A) ; off-sheet AH_PWM
AL_PWM: U3.28(GPIO1,EPWM1B) ; off-sheet AL_PWM
B_I_ADC: TP8.1 U3.13(ADCINB1) U3.17(ADCINB6) ; off-sheet B_I_ADC
B_V_ADC: TP7.1 U3.6(ADCINA7) ; off-sheet B_V_ADC
BH_PWM: U3.37(GPIO2,EPWM2A) ; off-sheet BH_PWM
BL_PWM: U3.38(GPIO3,EPWM2B) ; off-sheet BL_PWM
C_I_ADC: TP12.1 U3.4(ADCIND6/AIO6) U3.7(ADCINA3) ; off-sheet C_I_ADC
C_V_ADC: TP11.1 U3.16(ADCINB4) ; off-sheet C_V_ADC
CH_PWM: U3.39(GPIO4,EPWM3A) ; off-sheet CH_PWM
CL_PWM: U3.40(GPIO5,EPWM3B) ; off-sheet CL_PWM
DC_V_ADC: C33.1 D5.2(A) R39.2 R40.2 TP6.1 U3.14(ADCINB2) ; off-sheet DC_V_ADC
EN_GATE: U3.31(GPIO32,SDAA) ; off-sheet EN_GATE
FAULT: U3.48(GPIO28) ; off-sheet FAULT
IN_PWM: U3.1(GPIO29/SCITXDA) ; off-sheet IN_PWM
nSCS: U3.25(GPIO19,XCLKIN) ; off-sheet nSCS
OCTW: U3.36(GPIO33,SCLA) ; off-sheet OCTW
OUT_PWM: U3.41(GPIO6,EPWM4A) ; off-sheet OUT_PWM
PWRGD: U3.19(GPIO34,COMP2OUT) ; off-sheet PWRGD
RESETn: R45.1 U3.3(~{XRS}) U4.1(~{RESET})
SCIRXDA: J5.3 U3.42(GPIO7,EPWM4B)
SCITXDA: J5.2 U3.47(GPIO12~{,}TZ1)
SCLK: U3.24(GPIO18,SPICLKA) ; off-sheet SCLK
SDI: U3.27(GPIO16,SPISIMOA) ; off-sheet SDI
SDO: U3.26(GPIO17,SPISOMIA,) ; off-sheet SDO
TCK: J4.11 R42.2 U3.23(GPIO38,XCLKIN,)
TDI: J4.3 U3.20(GPIO35,[TDI])
TDIS: J4.4 R41.2
TDO: J4.7 U3.22(GPIO37,[TDO])
TMS: J4.1 U3.21(GPIO36,[TMS])
TRSTn: J4.2 R46.2 U3.2(~{TRST})
VDD: C28.1 U3.32(VDD)
VDD_1: C27.1 L3.2 U3.43(VDD) ; off-sheet VDD_1
VDDA: C32.1 L5.2 U3.11(VDDA) ; off-sheet VDDA
VDDIO_2: C31.1 L4.2 U3.35(VDDIO) ; off-sheet VDDIO_2
NetC34_1: C34.1 R71.1 U3.45(X1) Y1.1
NetC35_1: C35.1 U3.46(X2) Y1.3
NetC37_1: C37.1 R47.1 S1.2 U4.3(~{MR})
NetD8_1: D8.1(A) R43.2
NetJ4_9: J4.9 R42.1
NetR37_1: R37.1 R38.1 U2.1(+V)
NetR43_1: R43.1 U3.9(ADCINA2/COMP1A)
NetU3_5: U3.5(ADCINA4/COMP2A) U5.3(OUT)

Not connected (* = marked no-connect by the designer): J4 6 13 14; U2 3(NC); U3 30(TEST); U4 4(WDI); Y1 2(GND) 4(GND)

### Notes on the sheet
- (near C29) Select either filtered 3.3V or 3.0V Zener as reference for current measurements and ADC conversions.
  Install either R34 or R36
- VDD does NOT connect to 3p3V; VDD is 1.8V generated internally by TMS320F28035
- To utilize the on-chip VREG, the VREGENZ pin should be tied low and the appropriate recommended operating voltage should be supplied to the VDDIO and VDDA pins. In this case, the VDD voltage needed by
  the core logic will be generated by the VREG. Each VDD pin requires on the order of 1.2 µF (minimum) capacitance for proper regulation of the VREG. These capacitors (C5, C6, C7, C10, C11) should be located as close as possible
  to the VDD pins.
- (near U3) ECAP1
- (near Y1) NX3225GA20000 rated for Temp -40 to 150 C
  Alternate is:
  Kyocera CX3225CA20000D0HSSZ1 is -40 to 125C crystal 20 MHz
  in 2.5 x 3.2 mm 4 pad package
  If internal oscillator is used, do not install crystal or two caps.
- (near U4) nRESET
  H=normal operation
  L=powered down
  Leaving WDI unconnected disables the watchdog
- Place U3 in proximity to expected location of highest temperature.

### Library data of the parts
C26 C27 C30-C32 = GRM188R60J106ME47D: CAP, CERM, 10uF, 6.3V, +/-20%, X5R, 0603; Manufacturer: MuRata; Polarized: N; CompType: Capacitor; U/M: EA; Cap_F: 0.00001; Tolerance_%: 20; ESR_Ohm: 0.009; Value1: 0.009 ohm; VDC_V: 6.3; IRMS_A: 2.74; TaMin_C: -55; TaMax_C: 125
C28 = GRM188R71A225KE15D: CAP, CERM, 2.2uF, 10V, +/-10%, X7R, 0603; Manufacturer: MuRata; Polarized: N; CompType: Capacitor; U/M: EA; Cap_F: 0.0000022; Tolerance_%: 10; ESR_Ohm: 0.009; Value1: 0.009 ohm; TaMin_C: -55; TaMax_C: 125
C29 = C1608X7R1C105K: CAP, CERM, 1uF, 16V, +/-10%, X7R, 0603; Manufacturer: TDK; Polarized: N; CompType: Capacitor; U/M: EA; Cap_F: 0.000001; Tolerance_%: 10; ESR_Ohm: 0.0057; Value1: 0.0057 ohm; VDC_V: 16; TaMin_C: -55; TaMax_C: 125
C33 C38 = C0805C104K4RACTU: CAP, CERM, 0.1uF, 16V, +/-10%, X7R, 0805; Manufacturer: Kemet; Polarized: N; CompType: Capacitor; U/M: EA; Cap_F: 0.0000001; Tolerance_%: 10; ESR_Ohm: 0.064; Value1: 0.064 ohm; VDC_V: 16; IRMS_A: 1.64; TaMin_C: -55; TaMax_C: 125; Cap_Case: 0805
C34 C35 = 06035A120JAT2A: CAP, CERM, 12pF, 50V, +/-5%, C0G/NP0, 0603; Manufacturer: AVX; Polarized: N; CompType: Capacitor; U/M: EA; Cap_F: 0.000000000012; Tolerance_%: 5; ESR_Ohm: 0.363; Value1: 0.363 ohm; VDC_V: 50; TaMin_C: -55; TaMax_C: 125
C36 = GCM188R71H104KA57B: CAP, CERM, 0.1uF, 50V, +/-10%, X7R, 0603; Manufacturer: MuRata; Polarized: N; CompType: Capacitor; U/M: EA; Cap_F: 0.0000001; Tolerance_%: 10; ESR_Ohm: 0.02; Value1: 0.02 ohm; VDC_V: 50; IRMS_A: 1.84; TaMin_C: -55; TaMax_C: 125
C37 = Capacitor: CAP CER 2200PF 50V 10% X7R 0402; Manufacturer: Taiyo Yuden; Polarized: N; U/M: EA
D5 = CD0603-B0130L: Diode, Schottky, 35V, 0.1A, 0603 Diode; Manufacturer: Bourns; U/M: EA; Vf_V: 0.44; Io_A: 0.1; Vr_V: 35; TJmax_C: 125
D8 = LTST-C190KFKT: LED, Orange, SMD; Manufacturer: Lite-On; Type: AlInGaP; Vf_V: 2; Value2: 2V; Io_A: 0.02; Power_TotalModule: 0.075; Value1: 0.075W; U/M: EA
J4 = SBH11-PBPC-D07-ST-BK: Header (shrouded), 100 mil, 7x2, Gold plated, TH; Manufacturer: Sullins Connector Solutions; SymbolCreator: a0412235; CompType: Connector; U/M: EA
J5 = 0022112042: Header, 100mil, 4x1, White, TH; Manufacturer: Molex; SymbolCreator: a0412235; CompType: Connector; U/M: EA
L2 L4-L6 = BLM18SG121TN1D: 3A Ferrite Bead, 120 ohm @ 100MHz, SMD; Manufacturer: MuRata; Imax_A: 3; DCR_ohm: 0.025; Value1: 0.025 ohm; ZTyp@100MHz_Ohm: 120; U/M: EA
L3 = BLM18SG121TN1D: 3A Ferrite Bead, 120 ohm @ 100MHz, SMD; Manufacturer: MuRata; Value: 120 ohm; Imax_A: 3; DCR_ohm: 0.025; Value1: 0.025 ohm; ZTyp@100MHz_Ohm: 120; U/M: EA
R36 R38 R41 R42 R71 = ERJ-3GEY0R00V: as R3 on sheet BLDC Standard sheet 1
R37 = CRCW060331K6FKEA: RES, 31.6k ohm, 1%, 0.1W, 0603; Manufacturer: Vishay-Dale; CompType: Resistor; Res_ohm: 31600; Value_Code: 31k6; Tolerance_%: 1; Power_W: 0.1; VDC_V: 75; TempCo: 100 ppm/C; EIA_Code: E96; U/M: EA
R39 = CRCW060334K8FKEA: RES, 34.8k ohm, 1%, 0.1W, 0603; Manufacturer: Vishay-Dale; CompType: Resistor; Res_ohm: 34800; Value_Code: 34k8; Tolerance_%: 1; Power_W: 0.1; VDC_V: 75; TempCo: 100 ppm/C; EIA_Code: E96; U/M: EA
R40 = CRCW06034K99FKEA: RES, 4.99k ohm, 1%, 0.1W, 0603; Manufacturer: Vishay-Dale; CompType: Resistor; Res_ohm: 4990; Value_Code: 4k99; Tolerance_%: 1; Power_W: 0.1; VDC_V: 75; TempCo: 100 ppm/C; EIA_Code: E96; U/M: EA
R43 = CRCW06031K00JNEA: RES, 1.0k ohm, 5%, 0.1W, 0603; Manufacturer: Vishay-Dale; CompType: Resistor; Res_ohm: 1000; Value_Code: 1k00; Tolerance_%: 5; Power_W: 0.1; VDC_V: 75; TempCo: 200 ppm/C; EIA_Code: E24; U/M: EA
R45 R46 = CRCW06032K20JNEA: RES, 2.2k ohm, 5%, 0.1W, 0603; Manufacturer: Vishay-Dale; CompType: Resistor; Res_ohm: 2200; Value_Code: 2k20; Tolerance_%: 5; Power_W: 0.1; VDC_V: 75; TempCo: 200 ppm/C; EIA_Code: E24; U/M: EA
R47 = CRCW040247K0JNED: RES, 47k ohm, 5%, 0.063W, 0402; Manufacturer: Vishay-Dale; CompType: Resistor; Res_ohm: 47000; Value_Code: 47k0; Tolerance_%: 5; Power_W: 0.063; VDC_V: 50; TempCo: 200 ppm/C; EIA_Code: E24; U/M: EA
S1 = SKRKAEE010: Switch, Push Button, SMD; Manufacturer: Alps; Alternate Manufacturer: Any; Alternate PartNumber: Equivalent; SymbolCreator: a0412235; Circuit: SPST-NO; VDC_V: 12; SwitchFunction: Off-Mom; PositionCount: 1; CurrentRating_mA: 50
TP5 = 5012: Test Point, Multipurpose, White, TH; Manufacturer: Keystone; CompType: Test Point Loop; U/M: EA
TP6 = 5128: Test Point, Multipurpose, Grey, TH; Manufacturer: Keystone; SymbolCreator: a0412235; CompType: Test Point Loop; U/M: EA
TP7 = 5014: Test Point, Multipurpose, Yellow, TH; Manufacturer: Keystone; CompType: Test Point Loop; U/M: EA
TP8 = 5126: Test Point, Multipurpose, Green, TH; Manufacturer: Keystone; SymbolCreator: a0412235; CompType: Test Point Loop; U/M: EA
TP9 = 5010: Test Point, Multipurpose, Red, TH; Manufacturer: Keystone; CompType: Test Point Loop; U/M: EA
TP10 = 5013: Test Point, Multipurpose, Orange, TH; Manufacturer: Keystone; CompType: Test Point Loop; U/M: EA
TP11 = 5127: Test Point, Multipurpose, Blue, TH; Manufacturer: Keystone; CompType: Test Point Loop; U/M: EA
TP12 = 5129: Test Point, Multipurpose, Purple, TH; Manufacturer: Keystone; SymbolCreator: a0412235; CompType: Test Point Loop; U/M: EA
U2 = LM4040DEM3-3.0: Precision Micropower Shunt Voltage Reference, 3-pin SOT-23; Manufacturer: National Semiconductor; PackageTopMarking: RKD*XTT; PowerWise: N; CompType: Voltage Reference IC
U3 = TMS320F2802XPTA: IC, 32-Bit Piccolo Microcontrollers, xx MHz; Manufacturer: TI; Alternate Manufacturer: None; Area: 114.90 mm
U4 = TPS3828-33DBV: Processor Supervisory Circuit, DBV0005A; Alternate Manufacturer: None; Manufacturer: Texas Instruments; SymbolCreator: a0411947; CompType: IC; U/M: EA
U5 = LMT86DCKT: Analog Temperature Sensors with Class-AB Output, DCK0005A; Alternate Manufacturer: None; Manufacturer: Texas Instruments; SymbolCreator: a0799628; CompType: IC; U/M: EA
Y1 = NX3225SA-12.000000MHZ: Crystal, 12Mhz, 8pF, SMD; Manufacturer: NDK; SymbolCreator: a0412235; U/M: EA; TaMin_C: -10; TaMax_C: 70; Frequency Stability: ±15ppm

## Sheet BLDC Standard sheet 3.SchDoc
size 431 x 279 mm; Date: Not shown in title block; ApprovedBy: Not shown in title block; CheckedBy: Not shown in title block; Author: Not shown in title block; CompanyName: Not shown in title block; Engineer: Not shown in title block; Organization: Not shown in title block; Address1: Not shown in title block; Address2: Not shown in title block; Address3: Not shown in title block; Address4: Not shown in title block; DocumentNumber: 1; Revision: Use project parameter SCH_Rev; SheetNumber: 3; SheetTotal: 4; PageSetup: Record=PageOptions|CenterHorizontal=True|CenterVertical=True|PrintScale=0.96|XCorrection=1.00|YCorrection=1.00|PrintKind=0|BorderSize=5000000|LeftOffset=0|BottomOffset=0|Orientation=2|PaperLength=1000|PaperWidth=1000|Scale=100|PaperSource=15|PrintQuality=600|MediaType=1|DitherType=10|PaperKind=11x17|PrintScaleMode=1
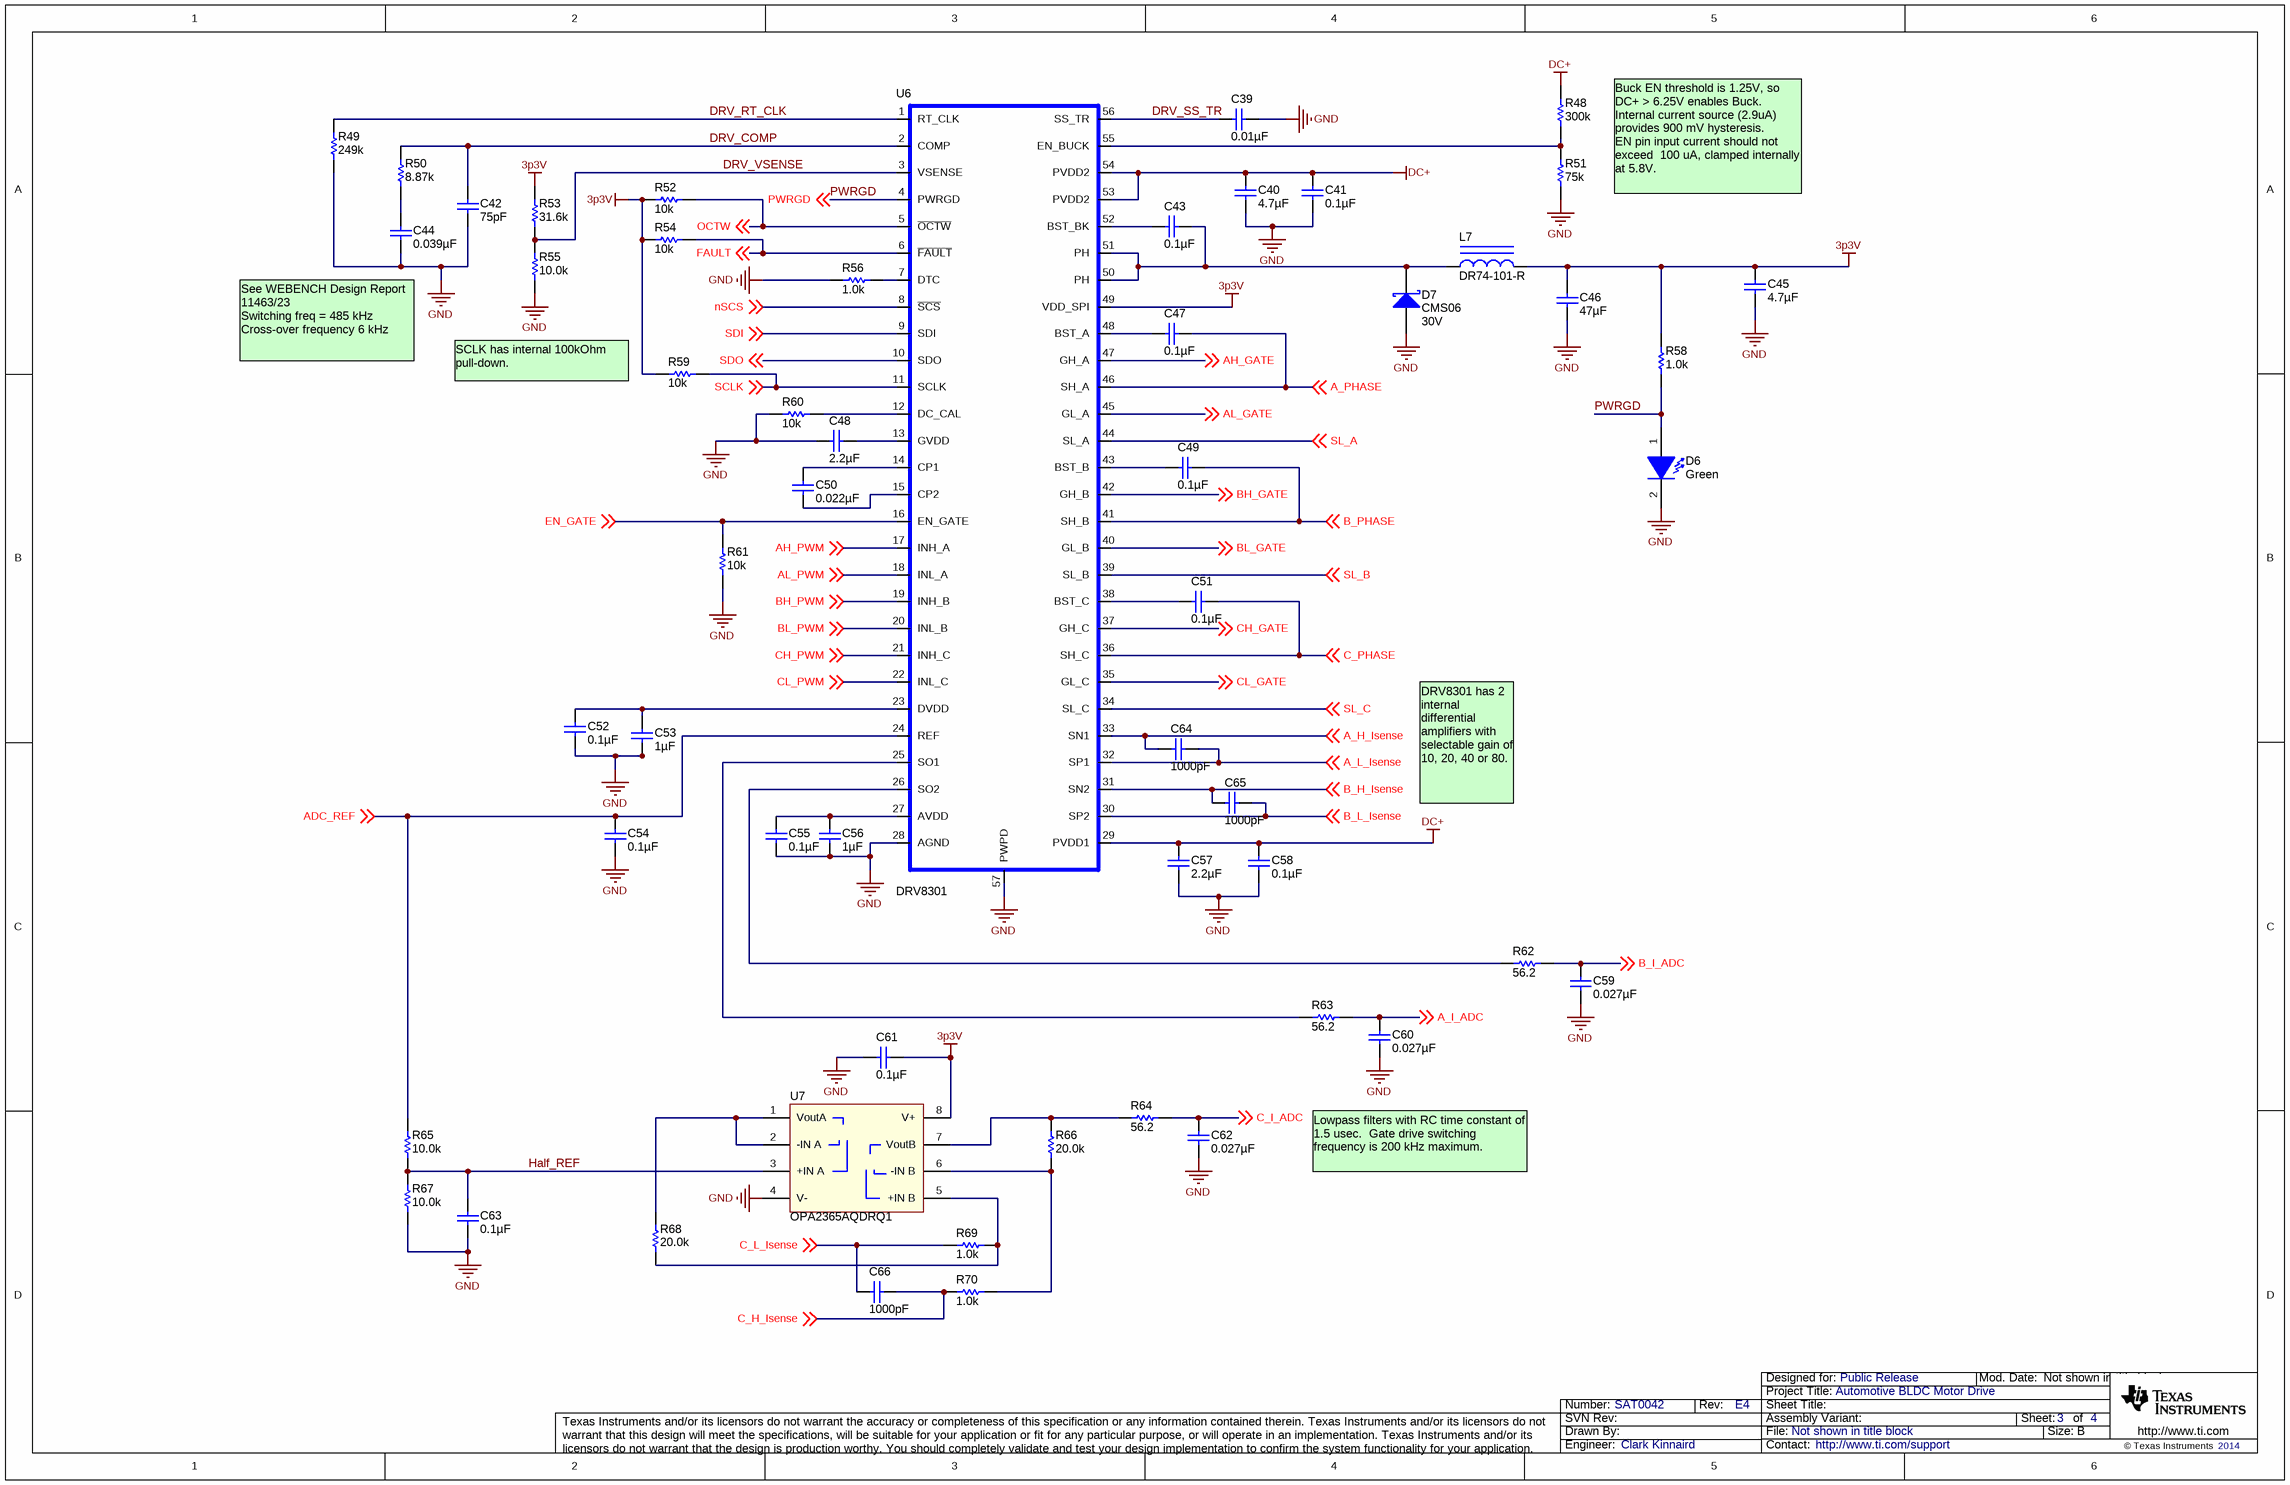
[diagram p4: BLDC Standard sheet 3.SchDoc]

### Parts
C39  ValueDisplayed: 0.01µF  [0805_HV]  (hidden comment: 08055C103JAT2A)
C40  ValueDisplayed: 4.7µF  [1206]  (hidden comment: GRM31CR71H475KA12L)
C41  ValueDisplayed: 0.1µF  [0603]  (hidden comment: 06035C104KAT2A)
C42  ValueDisplayed: 75pF  [0402]  (hidden comment: GRM1555C1H750JA01D)
C43  ValueDisplayed: 0.1µF  [0603]  (hidden comment: 06035C104KAT2A)
C44  ValueDisplayed: 0.039µF  [0402]  (hidden comment: GRM155R61A393KA01D)
C45  ValueDisplayed: 4.7µF  [1206]  (hidden comment: GRM31CR71H475KA12L)
C46  ValueDisplayed: 47µF  [1210]  (hidden comment: GRM32ER71A476KE15L)
C47  ValueDisplayed: 0.1µF  [0603]  (hidden comment: 06035C104KAT2A)
C48  ValueDisplayed: 2.2µF  [1206]  (hidden comment: GRM31MR71A225KA01L)
C49  ValueDisplayed: 0.1µF  [0603]  (hidden comment: 06035C104KAT2A)
C50  ValueDisplayed: 0.022µF  [0603]  (hidden comment: C0603C223K5RACTU)
C51  ValueDisplayed: 0.1µF  [0603]  (hidden comment: 06035C104KAT2A)
C52  ValueDisplayed: 0.1µF  [0603]  (hidden comment: 06035C104KAT2A)
C53  ValueDisplayed: 1µF  [0603]  (hidden comment: C1608X7R1C105K)
C54  ValueDisplayed: 0.1µF  [0603]  (hidden comment: 06035C104KAT2A)
C55  ValueDisplayed: 0.1µF  [0603]  (hidden comment: 06035C104KAT2A)
C56  ValueDisplayed: 1µF  [0603]  (hidden comment: C1608X7R1C105K)
C57  ValueDisplayed: 2.2µF  [1206]  (hidden comment: GRM31MR71A225KA01L)
C58  ValueDisplayed: 0.1µF  [0603]  (hidden comment: 06035C104KAT2A)
C59  ValueDisplayed: 0.027µF  [0603]  (hidden comment: GRM188R71C273KA01D)
C60  ValueDisplayed: 0.027µF  [0603]  (hidden comment: GRM188R71C273KA01D)
C61  ValueDisplayed: 0.1µF  [0603]  (hidden comment: 06035C104KAT2A)
C62  ValueDisplayed: 0.027µF  [0603]  (hidden comment: GRM188R71C273KA01D)
C63  ValueDisplayed: 0.1µF  [0603]  (hidden comment: 06035C104KAT2A)
C64  ValueDisplayed: 1000pF  [0402]  (hidden comment: GRM155R71H102KA01D)
C65  ValueDisplayed: 1000pF  [0402]  (hidden comment: GRM155R71H102KA01D)
C66  ValueDisplayed: 1000pF  [0402]  (hidden comment: GRM155R71H102KA01D)
D6  value Green  [LED_LTST-C190]  (hidden comment: LTST-C190GKT)
D7  CMS06  value 30V  [M-FLAT]
L7  DR74-101-R  [DR74]
R48  value 300k  [0402]  (hidden comment: CRCW0402300KJNED)
R49  value 249k  [0603]  (hidden comment: CRCW0603249KFKEA)
R50  value 8.87k  [0402]  (hidden comment: CRCW04028K87FKED)
R51  value 75k  [0402]  (hidden comment: CRCW040275K0JNED)
R52  value 10k  [0402]  (hidden comment: CRCW040210K0JNED)
R53  value 31.6k  [0603]  (hidden comment: CRCW060331K6FKEA)
R54  value 10k  [0402]  (hidden comment: CRCW040210K0JNED)
R55  value 10.0k  [0603]  (hidden comment: CRCW060310K0FKEA)
R56  value 1.0k  [0603]  (hidden comment: CRCW06031K00JNEA)
R58  value 1.0k  [0402]  (hidden comment: CRCW04021K00JNED)
R59  value 10k  [0402]  (hidden comment: CRCW040210K0JNED)
R60  value 10k  [0402]  (hidden comment: CRCW040210K0JNED)
R61  value 10k  [0402]  (hidden comment: CRCW040210K0JNED)
R62  value 56.2  [0603]  (hidden comment: CRCW060356R2FKEA)
R63  value 56.2  [0603]  (hidden comment: CRCW060356R2FKEA)
R64  value 56.2  [0603]  (hidden comment: CRCW060356R2FKEA)
R65  value 10.0k  [0603]  (hidden comment: CRCW060310K0FKEA)
R66  value 20.0k  [0603]  (hidden comment: CRCW060320K0FKEA)
R67  value 10.0k  [0603]  (hidden comment: CRCW060310K0FKEA)
R68  value 20.0k  [0603]  (hidden comment: CRCW060320K0FKEA)
R69  value 1.0k  [0603]  (hidden comment: CRCW06031K00JNEA)
R70  value 1.0k  [0603]  (hidden comment: CRCW06031K00JNEA)
U6  DRV8301  [DCA_56P]
U7  OPA2365AQDRQ1  [OPA2365AQDRQ1]

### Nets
3p3V: C45.1 C46.1 C61.2 L7.2 R52.1 R53.2 R54.1 R58.2 R59.1 U6.49(VDD_SPI) U7.8(V+)
DC+: C40.1 C41.1 C57.1 C58.1 R48.2 U6.29(PVDD1) U6.53(PVDD2) U6.54(PVDD2)
GND: C39.1 C40.2 C41.2 C42.2 C44.2 C45.2 C46.2 C48.2 C52.2 C53.2 C54.2 C55.2 C56.2 C57.2 C58.2 C59.2 C60.2 C61.1 C62.2 C63.2 D6.2(K) D7.2(A) R49.1 R51.1 R55.1 R56.1 R60.1 R61.1 R67.2 U6.28(AGND) U6.57(PWPD) U7.4(V-)
A_H_Isense: C64.1 U6.33(SN1) ; off-sheet A_H_Isense
A_I_ADC: C60.1 R63.2 ; off-sheet A_I_ADC
A_L_Isense: C64.2 U6.32(SP1) ; off-sheet A_L_Isense
A_PHASE: C47.2 U6.46(SH_A) ; off-sheet A_PHASE
ADC_REF: C54.1 R65.2 U6.24(REF) ; off-sheet ADC_REF
AH_GATE: U6.47(GH_A) ; off-sheet AH_GATE
AH_PWM: U6.17(INH_A) ; off-sheet AH_PWM
AL_GATE: U6.45(GL_A) ; off-sheet AL_GATE
AL_PWM: U6.18(INL_A) ; off-sheet AL_PWM
B_H_Isense: C65.1 U6.31(SN2) ; off-sheet B_H_Isense
B_I_ADC: C59.1 R62.2 ; off-sheet B_I_ADC
B_L_Isense: C65.2 U6.30(SP2) ; off-sheet B_L_Isense
B_PHASE: C49.2 U6.41(SH_B) ; off-sheet B_PHASE
BH_GATE: U6.42(GH_B) ; off-sheet BH_GATE
BH_PWM: U6.19(INH_B) ; off-sheet BH_PWM
BL_GATE: U6.40(GL_B) ; off-sheet BL_GATE
BL_PWM: U6.20(INL_B) ; off-sheet BL_PWM
C_H_Isense: C66.2 R70.1 ; off-sheet C_H_Isense
C_I_ADC: C62.1 R64.2 ; off-sheet C_I_ADC
C_L_Isense: C66.1 R69.1 ; off-sheet C_L_Isense
C_PHASE: C51.2 U6.36(SH_C) ; off-sheet C_PHASE
CH_GATE: U6.37(GH_C) ; off-sheet CH_GATE
CH_PWM: U6.21(INH_C) ; off-sheet CH_PWM
CL_GATE: U6.35(GL_C) ; off-sheet CL_GATE
CL_PWM: U6.22(INL_C) ; off-sheet CL_PWM
DRV_COMP: C42.1 R50.2 U6.2(COMP)
DRV_RT_CLK: R49.2 U6.1(RT_CLK)
DRV_SS_TR: C39.2 U6.56(SS_TR)
DRV_VSENSE: R53.1 R55.2 U6.3(VSENSE)
EN_GATE: R61.2 U6.16(EN_GATE) ; off-sheet EN_GATE
FAULT: R54.2 U6.6(~{FAULT}) ; off-sheet FAULT
Half_REF: C63.1 R65.1 R67.1 U7.3(+IN_A)
nSCS: U6.8(~{SCS}) ; off-sheet nSCS
OCTW: R52.2 U6.5(~{OCTW}) ; off-sheet OCTW
PWRGD: D6.1(A) R58.1 U6.4(PWRGD) ; off-sheet PWRGD
SCLK: R59.2 U6.11(SCLK) ; off-sheet SCLK
SDI: U6.9(SDI) ; off-sheet SDI
SDO: U6.10(SDO) ; off-sheet SDO
SL_A: U6.44(SL_A) ; off-sheet SL_A
SL_B: U6.39(SL_B) ; off-sheet SL_B
SL_C: U6.34(SL_C) ; off-sheet SL_C
NetC43_1: C43.1 D7.1(K) L7.1 U6.50(PH) U6.51(PH)
NetC43_2: C43.2 U6.52(BST_BK)
NetC44_1: C44.1 R50.1
NetC47_1: C47.1 U6.48(BST_A)
NetC48_1: C48.1 U6.13(GVDD)
NetC49_1: C49.1 U6.43(BST_B)
NetC50_1: C50.1 U6.14(CP1)
NetC50_2: C50.2 U6.15(CP2)
NetC51_1: C51.1 U6.38(BST_C)
NetC52_1: C52.1 C53.1 U6.23(DVDD)
NetC55_1: C55.1 C56.1 U6.27(AVDD)
NetR48_1: R48.1 R51.2 U6.55(EN_BUCK)
NetR56_2: R56.2 U6.7(DTC)
NetR60_2: R60.2 U6.12(DC_CAL)
NetR62_1: R62.1 U6.26(SO2)
NetR63_1: R63.1 U6.25(SO1)
NetR64_1: R64.1 R66.2 U7.7(VoutB)
NetR66_1: R66.1 R70.2 U7.6(-IN_B)
NetR68_1: R68.1 R69.2 U7.5(+IN_B)
NetR68_2: R68.2 U7.1(VoutA) U7.2(-IN_A)

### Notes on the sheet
- Buck EN threshold is 1.25V, so DC+ > 6.25V enables Buck.
  Internal current source (2.9uA) provides 900 mV hysteresis.
  EN pin input current should not exceed  100 uA, clamped internally at 5.8V.
- (near C44) See WEBENCH Design Report 11463/23
  Switching freq = 485 kHz
  Cross-over frequency 6 kHz
- SCLK has internal 100kOhm pull-down.
- DRV8301 has 2 internal differential amplifiers with selectable gain of 10, 20, 40 or 80.
- Lowpass filters with RC time constant of 1.5 usec.  Gate drive switching frequency is 200 kHz maximum.

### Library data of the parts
C39 = 08055C103JAT2A: CAP, CERM, 0.01uF, 50V, +/-5%, X7R, 0805; Manufacturer: AVX; Polarized: N; CompType: Capacitor; U/M: EA; Cap_F: 0.00000001; Tolerance_%: 5; ESR_Ohm: 0.078; Value1: 0.078 ohm; VDC_V: 50; TaMin_C: -55; TaMax_C: 125; Cap_Case: 0805
C40 C45 = GRM31CR71H475KA12L: CAP, CERM, 4.7uF, 50V, +/-10%, X7R, 1206; Manufacturer: MuRata; Polarized: N; CompType: Capacitor; U/M: EA; Cap_F: 0.0000047; Tolerance_%: 10; Value1: Unknown; VDC_V: 50; TaMin_C: -55; TaMax_C: 125; Cap_Case: 2220
C41 C43 C47 C49 C51 C52 C54 C55 C58 C61 C63 = 06035C104KAT2A: CAP, CERM, 0.1uF, 50V, +/-10%, X7R, 0603; Manufacturer: AVX; Polarized: N; CompType: Capacitor; U/M: EA; Cap_F: 0.0000001; Tolerance_%: 10; Value1: Unknown; VDC_V: 50; TaMin_C: -55; TaMax_C: 125
C42 = GRM1555C1H750JA01D: CAP, CERM, 75pF, 50V, +/-5%, C0G/NP0, 0402; Manufacturer: MuRata; Polarized: N; CompType: Capacitor; U/M: EA; Cap_F: 0.000000000075; Tolerance_%: 5; Value1: Unknown; VDC_V: 50; TaMin_C: -55; TaMax_C: 125
C44 = GRM155R61A393KA01D: CAP, CERM, 0.039uF, 10V, +/-10%, X5R, 0402; Manufacturer: MuRata; Polarized: N; CompType: Capacitor; U/M: EA; Cap_F: 0.000000039; Tolerance_%: 10; Value1: Unknown; TaMin_C: -55; TaMax_C: 85
C46 = GRM32ER71A476KE15L: CAP, CERM, 47uF, 10V, +/-10%, X7R, 1210; Manufacturer: MuRata; Polarized: N; CompType: Capacitor; U/M: EA; Cap_F: 0.000047; Tolerance_%: 10; Value1: Unknown; TaMin_C: -55; TaMax_C: 125
C48 C57 = GRM31MR71A225KA01L: CAP, CERM, 2.2uF, 10V, +/-10%, X7R, 1206; Manufacturer: MuRata; Polarized: N; CompType: Capacitor; U/M: EA; Cap_F: 0.0000022; Tolerance_%: 10; Value1: Unknown; TaMin_C: -55; TaMax_C: 125
C50 = C0603C223K5RACTU: CAP, CERM, 0.022uF, 50V, +/-10%, X7R, 0603; Manufacturer: Kemet; Polarized: N; CompType: Capacitor; U/M: EA; Cap_F: 0.000000022; Tolerance_%: 10; Value1: Unknown; VDC_V: 50; TaMin_C: -55; TaMax_C: 125
C53 C56 = C1608X7R1C105K: as C29 on sheet BLDC Standard sheet 2
C59 C60 C62 = GRM188R71C273KA01D: CAP, CERM, 0.027uF, 16V, +/-10%, X7R, 0603; Manufacturer: MuRata; Polarized: N; CompType: Capacitor; U/M: EA; Cap_F: 0.000000027; Tolerance_%: 10; Value1: Unknown; VDC_V: 16; TaMin_C: -55; TaMax_C: 125
C64-C66 = GRM155R71H102KA01D: CAP, CERM, 1000pF, 50V, +/-10%, X7R, 0402; Manufacturer: MuRata; Polarized: N; CompType: Capacitor; U/M: EA; Cap_F: 0.000000001; Tolerance_%: 10; Value1: Unknown; VDC_V: 50; TaMin_C: -55; TaMax_C: 125
D6 = LTST-C190GKT: LED, Green, SMD; Manufacturer: Lite-On; Vf_V: 2.1; Value2: 2.1V; Io_A: 0.02; Power_TotalModule: 0.1; Value1: 0.1W; U/M: EA
D7 = CMS06: Diode, Schottky, 30V, 2A, M-FLAT; Manufacturer: Toshiba; U/M: EA; Vf_V: 0.32; Value2: 0.32V; Io_A: 2; Vr_V: 30; TJmax_C: 125; RJC_CperW: 16
L7 = DR74-101-R: Inductor, Shielded Drum Core, Ferrite, 100uH, 0.86A, 0.383 ohm, SMD; Manufacturer: Coiltronics; Ind_H: 100.0E-6; ValueDisplayed: 100µH; Imax_A: 0.86; Irms: 0.86A @ 40C rise; Isat: 0.99A @ 30% inductance drop; DCR_ohm: 0.383; U/M: EA
R48 = CRCW0402300KJNED: RES, 300k ohm, 5%, 0.063W, 0402; Manufacturer: Vishay-Dale; CompType: Resistor; Res_ohm: 300000; Tolerance_%: 5; Power_W: 0.063; VDC_V: 50; TempCo: 200 ppm/C; EIA_Code: E24; U/M: EA
R49 = CRCW0603249KFKEA: RES, 249k ohm, 1%, 0.1W, 0603; Manufacturer: Vishay-Dale; CompType: Resistor; Res_ohm: 249000; Tolerance_%: 1; Power_W: 0.1; VDC_V: 75; TempCo: 100 ppm/C; EIA_Code: E96; U/M: EA
R50 = CRCW04028K87FKED: RES, 8.87k ohm, 1%, 0.063W, 0402; Manufacturer: Vishay-Dale; CompType: Resistor; Res_ohm: 8870; Value_Code: 8k87; Tolerance_%: 1; Power_W: 0.063; VDC_V: 50; TempCo: 100 ppm/C; EIA_Code: E96; U/M: EA
R51 = CRCW040275K0JNED: RES, 75k ohm, 5%, 0.063W, 0402; Manufacturer: Vishay-Dale; CompType: Resistor; Res_ohm: 75000; Value_Code: 75k0; Tolerance_%: 5; Power_W: 0.063; VDC_V: 50; TempCo: 200 ppm/C; EIA_Code: E24; U/M: EA
R52 R54 R59-R61 = CRCW040210K0JNED: as R6 on sheet BLDC Standard sheet 1
R53 = CRCW060331K6FKEA: as R37 on sheet BLDC Standard sheet 2
R55 R65 R67 = CRCW060310K0FKEA: RES, 10.0k ohm, 1%, 0.1W, 0603; Manufacturer: Vishay-Dale; CompType: Resistor; Res_ohm: 10000; Value_Code: 10k0; Tolerance_%: 1; Power_W: 0.1; VDC_V: 75; TempCo: 100 ppm/C; EIA_Code: E96; U/M: EA
R56 R69 R70 = CRCW06031K00JNEA: as R43 on sheet BLDC Standard sheet 2
R58 = CRCW04021K00JNED: RES, 1.0k ohm, 5%, 0.063W, 0402; Manufacturer: Vishay-Dale; CompType: Resistor; Res_ohm: 1000; Value_Code: 1k00; Tolerance_%: 5; Power_W: 0.063; VDC_V: 50; TempCo: 200 ppm/C; EIA_Code: E24; U/M: EA
R62-R64 = CRCW060356R2FKEA: RES, 56.2 ohm, 1%, 0.1W, 0603; Manufacturer: Vishay-Dale; CompType: Resistor; Value_Code: 56R2; Tolerance_%: 1; Power_W: 0.1; VDC_V: 75; TempCo: 100 ppm/C; EIA_Code: E96; U/M: EA
R66 R68 = CRCW060320K0FKEA: RES, 20.0k ohm, 1%, 0.1W, 0603; Manufacturer: Vishay-Dale; CompType: Resistor; Res_ohm: 20000; Value_Code: 20k0; Tolerance_%: 1; Power_W: 0.1; VDC_V: 75; TempCo: 100 ppm/C; EIA_Code: E96; U/M: EA
U6 = DRV8301: IC, 3 Phase Pre-Driver with Dual Current Shunt Amplifiers and Buck Converter; Manufacturer: TI; Alternate Manufacturer: None; Area: 154.44 mm
U7 = OPA2365AQDRQ1: IC OPAMP GP RRIO 50MHZ LN 8SOIC; Manufacturer: Texas Instruments; Amplifier Type: General Purpose; Number of Circuits: 2; Output Type: Rail-to-Rail; Slew Rate: 25 V/µs; Current - Input Bias: 0.2pA; Voltage - Input Offset: 100µV; Current - Supply: 4.6mA; Current - Output / Channel: 65mA; Voltage - Supply, Single/Dual (±): 2.2 V ~ 5.5 V, ±1.1 V ~ 2.25 V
